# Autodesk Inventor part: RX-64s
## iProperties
Created: 2008-12
Part Number: RX-64s
Material: Aluminum-6061
Document SubType Name: Sheet Metal
Designer: Administrator
Density: 1 g/cm^3
Author: Administrator
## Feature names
1. Hole1
2. Hole2
3. Hole3
4. Corner Round1
5. Corner Round2
6. Hole4
7. Plate1
8. Plate2
9. Bend1
